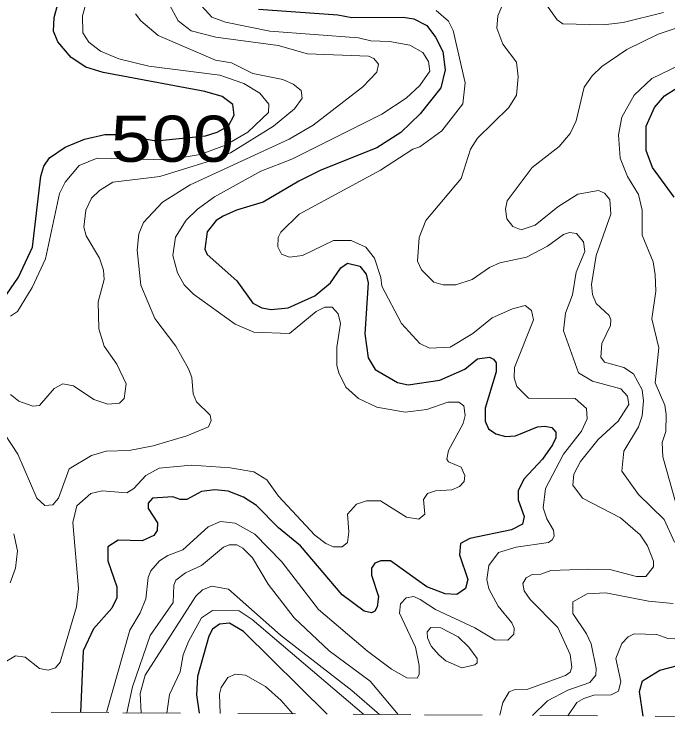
# Model space of a CAD drawing. Extents: x 577 to 602.9, y 7483.8 to 7511.6.
# Drawn here: x 599.345 to 600.48, y 7483.775 to 7485.008 of the extents above; entities that cross this region are included whole.
import ezdxf
from ezdxf.enums import TextEntityAlignment as Align

# ---------------------------------------------------------------- set-up
doc = ezdxf.new("R2010")
doc.units = 0
doc.header["$LTSCALE"] = 0.032
doc.linetypes.add('SHORT_DASHED', pattern=[2.7, 1.5, -1.2])
for name, color, linetype, lineweight in [('1', 7, 'Continuous', 25), ('2', 7, 'Continuous', 13), ('62', 7, 'SHORT_DASHED', 13)]:
    doc.layers.add(name, color=color, linetype=linetype, lineweight=lineweight)
doc.layers.add('61', color=7, linetype='Continuous')

msp = doc.modelspace()

# ---------------------------------------------------------------- linework, layer by layer
at = {"layer": '1'}
for points in [[(599.7065, 7484.8652), (599.6763, 7484.8739), (599.4998, 7484.9065), (599.4695, 7484.9161), (599.4441, 7484.9328), (599.421, 7484.9598), (599.4139, 7484.9781), (599.4147, 7485.002), (599.421, 7485.025), (599.4282, 7485.0369), (599.4847, 7485.0982), (599.5713, 7485.1666), (599.7455, 7485.3129), (599.7749, 7485.3439), (599.8075, 7485.3908), (599.821, 7485.4298), (599.8242, 7485.4886), (599.7987, 7485.5888), (599.7924, 7485.6484), (599.7924, 7485.6961), (599.8051, 7485.7542)], [(599.7693, 7485.0163), (599.9069, 7485.0067), (599.9315, 7485.002), (600.0206, 7485.0028), (600.0389, 7484.9996), (600.0612, 7484.9884), (600.0763, 7484.9678), (600.089, 7484.9431), (600.093, 7484.9113), (600.0858, 7484.8803), (600.05, 7484.835), (600.0166, 7484.8024), (599.9745, 7484.7761), (599.8775, 7484.7372), (599.8393, 7484.7181), (599.7773, 7484.6815), (599.7312, 7484.668), (599.7081, 7484.6576), (599.6962, 7484.6497), (599.6803, 7484.6306), (599.6763, 7484.6004), (599.6803, 7484.5909), (599.732, 7484.5455), (599.7598, 7484.5066), (599.7749, 7484.4986), (599.7916, 7484.4954), (599.821, 7484.4986), (599.8671, 7484.5193), (599.8942, 7484.5416), (599.9125, 7484.5678), (599.9236, 7484.5757), (599.9451, 7484.571), (599.9562, 7484.5567), (599.9594, 7484.5416), (599.9538, 7484.4533), (599.9594, 7484.4119), (599.9721, 7484.3913), (600.0103, 7484.369), (600.0293, 7484.365), (600.0842, 7484.373), (600.1272, 7484.3921), (600.1494, 7484.4103), (600.1701, 7484.4127), (600.1773, 7484.4096)], [(600.4905, 7484.6903), (600.4532, 7484.7419), (600.442, 7484.7714), (600.442, 7484.8135), (600.4564, 7484.8461), (600.4739, 7484.866), (600.4977, 7484.8811)], [(599.3328, 7484.5225), (599.3527, 7484.5519), (599.3773, 7484.6036), (599.3916, 7484.7268), (599.3972, 7484.7443), (599.4067, 7484.7586), (599.4338, 7484.7769), (599.4672, 7484.7912), (599.5029, 7484.7992), (599.5284, 7484.7992), (599.592, 7484.7883), (599.6776, 7484.7968), (599.6978, 7484.8032), (599.7176, 7484.8143), (599.7272, 7484.8326), (599.7248, 7484.8509), (599.7065, 7484.8652)], [(600.1773, 7484.4096), (600.182, 7484.4032), (600.182, 7484.3873), (600.1629, 7484.3245), (600.1629, 7484.3022), (600.1685, 7484.2887), (600.1812, 7484.2799), (600.1979, 7484.2752), (600.2154, 7484.2768), (600.2536, 7484.2919), (600.2663, 7484.2935), (600.2782, 7484.2911), (600.2854, 7484.2831), (600.2854, 7484.2728), (600.2798, 7484.2609), (600.2623, 7484.2362), (600.2297, 7484.2012), (600.2202, 7484.1813), (600.2202, 7484.1654), (600.2305, 7484.1368), (600.2273, 7484.1233), (600.2083, 7484.1137), (600.1359, 7484.0986), (600.12, 7484.0899), (600.1184, 7484.07), (600.1327, 7484.0271), (600.1287, 7484.012), (600.1136, 7484.0016), (600.093, 7484.0024), (600.0612, 7484.0144), (599.9983, 7484.0597), (599.9816, 7484.0597), (599.9713, 7484.0557), (599.9657, 7484.047), (599.9657, 7484.035), (599.9777, 7483.9977), (599.9753, 7483.9802), (599.9713, 7483.9722), (599.9657, 7483.9698), (599.953, 7483.9722), (599.9148, 7484.0008), (599.8425, 7484.0859), (599.8043, 7484.1169), (599.7661, 7484.1559), (599.7431, 7484.1702), (599.7168, 7484.1805), (599.6938, 7484.1829), (599.6707, 7484.1797), (599.6453, 7484.1662), (599.6333, 7484.1662), (599.6206, 7484.171), (599.5856, 7484.1686), (599.5777, 7484.1599), (599.5777, 7484.1503), (599.5944, 7484.1257), (599.5936, 7484.1122), (599.588, 7484.1034), (599.5674, 7484.0947), (599.526, 7484.0955), (599.5077, 7484.0843), (599.5077, 7484.0597), (599.5236, 7484.0144), (599.5236, 7483.9953), (599.5149, 7483.9778), (599.4831, 7483.942), (599.465, 7483.9037), (599.4604, 7483.7968)], [(599.8885, 7483.7939), (599.7431, 7483.9372), (599.7192, 7483.9515), (599.7017, 7483.9499), (599.6898, 7483.9412), (599.6834, 7483.9293), (599.6636, 7483.8593), (599.662, 7483.8275), (599.6665, 7483.7954)], [(600.4367, 7483.7904), (600.4304, 7483.833), (600.4358, 7483.8515), (600.4659, 7483.8704), (600.5104, 7483.8816)]]:
    msp.add_lwpolyline(points, dxfattribs=at)
at = {"layer": '2'}
for points in [[(599.6588, 7485.0354), (599.6882, 7485.0028), (599.7121, 7484.994), (599.7892, 7484.9781), (599.9427, 7484.967), (599.9641, 7484.9614), (599.9967, 7484.9606), (600.0317, 7484.9542), (600.0548, 7484.9415), (600.0643, 7484.9256), (600.0667, 7484.9089), (600.0492, 7484.8843), (600.0254, 7484.862), (599.9832, 7484.8342), (599.8274, 7484.7563), (599.7733, 7484.7356), (599.693, 7484.691), (599.6636, 7484.6696), (599.6437, 7484.6505), (599.6254, 7484.6211), (599.6206, 7484.5893), (599.6286, 7484.559), (599.6405, 7484.5384), (599.6564, 7484.5225), (599.7288, 7484.47), (599.7614, 7484.4565), (599.8234, 7484.4541), (599.8695, 7484.4923), (599.8846, 7484.4994), (599.8973, 7484.4994), (599.9077, 7484.4883), (599.9117, 7484.4716), (599.9053, 7484.4302), (599.9053, 7484.3984), (599.9085, 7484.3857), (599.9212, 7484.361), (599.9427, 7484.3412), (599.9745, 7484.3261), (600.0238, 7484.3173), (600.0612, 7484.3221), (600.0977, 7484.3348), (600.1168, 7484.3348), (600.1256, 7484.3284), (600.1279, 7484.3117), (600.1248, 7484.2982), (600.0993, 7484.2513), (600.0961, 7484.2362), (600.0993, 7484.2314), (600.1208, 7484.2219), (600.1272, 7484.2076), (600.1264, 7484.1972), (600.1184, 7484.1885), (600.1049, 7484.1829), (600.0763, 7484.1813), (600.0627, 7484.1766), (600.0556, 7484.1662), (600.058, 7484.1408), (600.0476, 7484.132), (600.0262, 7484.1352), (599.9808, 7484.1638), (599.957, 7484.1638), (599.9395, 7484.1583), (599.9236, 7484.1408), (599.926, 7484.1098), (599.9236, 7484.0915), (599.9148, 7484.0843), (599.8997, 7484.0843), (599.8862, 7484.0899), (599.8671, 7484.1042), (599.8043, 7484.1718), (599.7836, 7484.2004), (599.7614, 7484.2139), (599.72, 7484.2211), (599.6532, 7484.2259), (599.5968, 7484.2203), (599.5737, 7484.2076), (599.553, 7484.1853), (599.5411, 7484.1774)], [(600.2631, 7485.0322), (600.2878, 7484.998), (600.2973, 7484.9908), (600.3673, 7484.9892), (600.4023, 7484.9932), (600.4723, 7485.0107)], [(599.6143, 7485.025), (599.6302, 7484.9964), (599.6524, 7484.9789), (599.6954, 7484.9678), (599.8035, 7484.9535), (599.8544, 7484.9391), (599.9602, 7484.9352), (599.9697, 7484.9312), (599.9777, 7484.9209), (599.9745, 7484.9073), (599.9506, 7484.8819), (599.864, 7484.8151), (599.8226, 7484.7912), (599.6508, 7484.7117), (599.6031, 7484.6815), (599.5697, 7484.6465), (599.5618, 7484.6266), (599.5586, 7484.5988), (599.565, 7484.5376), (599.5896, 7484.4803), (599.6262, 7484.4318), (599.6477, 7484.3929), (599.654, 7484.3777), (599.6559, 7484.3493), (599.662, 7484.3356), (599.6858, 7484.3125), (599.6874, 7484.303), (599.6827, 7484.2919), (599.6453, 7484.2768), (599.5864, 7484.2593), (599.5451, 7484.2513), (599.5053, 7484.2497), (599.4799, 7484.2426), (599.4409, 7484.2195), (599.4226, 7484.1686), (599.4123, 7484.1567), (599.3988, 7484.1559), (599.3845, 7484.1686), (599.3519, 7484.245), (599.3169, 7484.2966)], [(599.7439, 7484.8875), (599.7025, 7484.9018), (599.5793, 7484.9177), (599.5268, 7484.9304), (599.495, 7484.9439), (599.4751, 7484.959), (599.4648, 7484.9757), (599.464, 7485.0051), (599.4711, 7485.0298)], [(600.1881, 7483.7919), (600.1932, 7483.814), (600.2043, 7483.8323), (600.213, 7483.8362), (600.2369, 7483.837), (600.3021, 7483.8609), (600.31, 7483.8664), (600.3132, 7483.8752), (600.31, 7483.8975), (600.2886, 7483.9444), (600.2409, 7483.9929), (600.2305, 7484.008), (600.2281, 7484.0207), (600.2337, 7484.0303), (600.244, 7484.0358), (600.2592, 7484.0366), (600.2766, 7484.043), (600.3426, 7484.0454), (600.3792, 7484.0446), (600.4253, 7484.0326), (600.4412, 7484.0326), (600.4548, 7484.0493), (600.4548, 7484.0589), (600.4444, 7484.0859), (600.4317, 7484.105), (600.3975, 7484.1344), (600.3315, 7484.1686), (600.3148, 7484.1909), (600.3164, 7484.21), (600.3283, 7484.2322), (600.3586, 7484.2704), (600.3935, 7484.3022), (600.4118, 7484.3308), (600.4094, 7484.3451), (600.3983, 7484.3579), (600.349, 7484.3714), (600.3244, 7484.3857), (600.2989, 7484.4589), (600.3021, 7484.4891), (600.314, 7484.5209), (600.3204, 7484.5606), (600.3355, 7484.5964), (600.3331, 7484.6131), (600.3212, 7484.6274), (600.3092, 7484.629), (600.2989, 7484.6258), (600.2711, 7484.6052), (600.2345, 7484.5861), (600.1884, 7484.5765), (600.1701, 7484.5686), (600.1399, 7484.5479), (600.112, 7484.5384), (600.0898, 7484.5384), (600.0739, 7484.5431), (600.0524, 7484.5646), (600.0453, 7484.5797), (600.0484, 7484.6203), (600.0596, 7484.6497), (600.1208, 7484.7229), (600.1375, 7484.7737), (600.1494, 7484.7928), (600.2035, 7484.8461), (600.217, 7484.8676), (600.2202, 7484.8994), (600.217, 7484.9248), (600.1932, 7484.9558), (600.1828, 7484.9837), (600.1844, 7485.0051), (600.1916, 7485.021)], [(599.5059, 7483.7965), (599.5459, 7483.9396), (599.5642, 7483.9698), (599.5737, 7483.9937), (599.5777, 7484.031), (599.5825, 7484.0422), (599.5976, 7484.0597), (599.6119, 7484.0692), (599.6381, 7484.0788), (599.6819, 7484.1185), (599.7033, 7484.1281), (599.7288, 7484.1249), (599.763, 7484.1058), (599.8099, 7484.0581), (599.8735, 7483.9754), (599.9586, 7483.903), (599.9999, 7483.872), (600.027, 7483.8569), (600.0445, 7483.8561), (600.0484, 7483.8625), (600.0484, 7483.8784), (600.0421, 7483.9102), (600.0142, 7483.969), (600.0158, 7483.9849), (600.0254, 7483.9953), (600.0389, 7483.9977), (600.05, 7483.9929), (600.0763, 7483.9754), (600.1446, 7483.9436), (600.1796, 7483.9229), (600.2019, 7483.9221), (600.2122, 7483.9324), (600.213, 7483.9428), (600.2091, 7483.9523), (600.1852, 7483.981), (600.1693, 7484.0112), (600.1653, 7484.0271), (600.1693, 7484.0517), (600.186, 7484.074), (600.2162, 7484.0835), (600.2727, 7484.0915), (600.279, 7484.0963), (600.2822, 7484.1026), (600.2814, 7484.113), (600.2695, 7484.1328), (600.2631, 7484.1519), (600.2671, 7484.1853), (600.2989, 7484.245), (600.3299, 7484.2847), (600.3395, 7484.3062), (600.3387, 7484.3237), (600.3188, 7484.3412), (600.2377, 7484.342), (600.2178, 7484.3618), (600.213, 7484.377), (600.2138, 7484.3952), (600.2464, 7484.4779), (600.2432, 7484.4938), (600.2321, 7484.5026), (600.2099, 7484.497), (600.1749, 7484.4811), (600.1415, 7484.4541), (600.1017, 7484.4302), (600.0659, 7484.4286), (600.0492, 7484.4366), (600.0174, 7484.4716), (599.9832, 7484.536), (599.9816, 7484.5511), (599.9705, 7484.5845), (599.9554, 7484.6036), (599.93, 7484.6155), (599.8997, 7484.6155), (599.8457, 7484.5893), (599.8234, 7484.5861), (599.8091, 7484.5916), (599.8027, 7484.6044), (599.8035, 7484.6203), (599.8083, 7484.6298), (599.8401, 7484.6608), (599.9808, 7484.7372), (600.0373, 7484.7737), (600.0492, 7484.7777), (600.0874, 7484.8056), (600.124, 7484.8525), (600.1279, 7484.889), (600.1073, 7484.9797), (600.0993, 7484.9956), (600.0779, 7485.0139)], [(599.8115, 7484.8946), (599.7598, 7484.9049), (599.7224, 7484.9232), (599.6946, 7484.928), (599.5952, 7484.9709), (599.565, 7484.9964), (599.5562, 7485.0083)], [(600.4913, 7484.0923), (600.4731, 7484.1312), (600.4285, 7484.175), (600.3999, 7484.2155), (600.4031, 7484.2497), (600.4285, 7484.2919), (600.4349, 7484.311), (600.4373, 7484.3372), (600.4349, 7484.3563), (600.4198, 7484.3841), (600.4031, 7484.3952), (600.3697, 7484.404), (600.3633, 7484.4127), (600.3649, 7484.4366), (600.38, 7484.4676), (600.3808, 7484.4779), (600.3776, 7484.4851), (600.3554, 7484.5058), (600.349, 7484.5217), (600.3474, 7484.5392), (600.3554, 7484.5893), (600.3808, 7484.6608), (600.3792, 7484.6863), (600.3697, 7484.6974), (600.3593, 7484.7022), (600.3236, 7484.6958), (600.2886, 7484.6736), (600.2496, 7484.6417), (600.225, 7484.6338), (600.2106, 7484.6394), (600.2003, 7484.6529), (600.1979, 7484.6696), (600.2011, 7484.6839), (600.244, 7484.7419), (600.291, 7484.7785), (600.31, 7484.8008), (600.3204, 7484.823), (600.3347, 7484.8811), (600.3482, 7484.901), (600.3649, 7484.9169), (600.4086, 7484.9463), (600.4627, 7484.9733), (600.508, 7484.9884)], [(600.4929, 7484.1623), (600.4707, 7484.2402), (600.4699, 7484.2648), (600.4762, 7484.2839), (600.477, 7484.3133), (600.4746, 7484.33), (600.4579, 7484.3682), (600.4643, 7484.4294), (600.4516, 7484.4795), (600.4587, 7484.5272), (600.4579, 7484.5559), (600.454, 7484.5781), (600.4349, 7484.6243), (600.4349, 7484.668), (600.4285, 7484.695), (600.4094, 7484.726), (600.3967, 7484.7578), (600.3943, 7484.7984), (600.3999, 7484.8294), (600.4214, 7484.8676), (600.4516, 7484.8962), (600.5001, 7484.9193)], [(599.3391, 7484.3483), (599.3534, 7484.3364), (599.3781, 7484.3277), (599.3892, 7484.3292), (599.4147, 7484.3587), (599.4298, 7484.3666), (599.4481, 7484.3634), (599.4839, 7484.3396), (599.5077, 7484.3316), (599.5284, 7484.3332), (599.5363, 7484.3412), (599.5395, 7484.3666), (599.5236, 7484.4008), (599.5014, 7484.4318), (599.4926, 7484.462), (599.491, 7484.509), (599.5014, 7484.5479), (599.5006, 7484.5638), (599.4934, 7484.5845), (599.4703, 7484.6235), (599.4664, 7484.6386), (599.4695, 7484.668), (599.4799, 7484.6887), (599.4934, 7484.7022), (599.5165, 7484.7165), (599.5984, 7484.726), (599.6803, 7484.7515), (599.7208, 7484.7674), (599.7956, 7484.8135), (599.8321, 7484.8437), (599.8449, 7484.862), (599.8433, 7484.8755), (599.8298, 7484.8867), (599.8115, 7484.8946)], [(599.3391, 7484.4843), (599.3511, 7484.4923), (599.3765, 7484.5336), (599.3996, 7484.5837), (599.4242, 7484.6966), (599.4338, 7484.7165), (599.4585, 7484.7452), (599.4895, 7484.7581), (599.6121, 7484.7551), (599.6681, 7484.7642), (599.7121, 7484.7809), (599.751, 7484.8032), (599.7868, 7484.8374), (599.7876, 7484.8517), (599.7717, 7484.8708), (599.7439, 7484.8875)], [(599.5411, 7484.1774), (599.4982, 7484.1813), (599.4783, 7484.1766), (599.4544, 7484.1551), (599.4473, 7484.1265), (599.4568, 7484.012), (599.4536, 7483.9802), (599.425, 7483.8839), (599.4171, 7483.8744), (599.4043, 7483.8704), (599.3892, 7483.8728), (599.3646, 7483.8927), (599.3479, 7483.8951), (599.289, 7483.8601)], [(599.3383, 7484.0215), (599.3479, 7484.047), (599.3511, 7484.0772), (599.3447, 7484.1066)], [(599.5409, 7483.7963), (599.5506, 7483.8414), (599.5817, 7483.9301), (599.6214, 7483.9873), (599.6222, 7484.0175), (599.6262, 7484.0263), (599.6429, 7484.039), (599.6707, 7484.0517), (599.7089, 7484.0835), (599.7184, 7484.0875), (599.732, 7484.0875), (599.7423, 7484.0819), (599.759, 7484.0652), (599.786, 7484.0191), (599.8313, 7483.9611), (599.8918, 7483.9038), (599.9633, 7483.8513), (600.0118, 7483.7931)], [(599.9795, 7483.7933), (599.9315, 7483.835), (599.8074, 7483.9309), (599.7176, 7484.0104), (599.6882, 7484.0159), (599.6723, 7484.0096), (599.6604, 7483.9984), (599.5729, 7483.8612), (599.5641, 7483.8296), (599.5657, 7483.7961)], [(600.2446, 7483.7916), (600.2711, 7483.8171), (600.3061, 7483.8354), (600.3442, 7483.849), (600.3546, 7483.8617), (600.3554, 7483.8728), (600.3466, 7483.9157), (600.3387, 7483.9332), (600.3148, 7483.9682), (600.3148, 7483.9889), (600.3395, 7484.0024), (600.3721, 7484.004), (600.446, 7483.9897), (600.489, 7483.9857)], [(599.6104, 7483.7958), (599.615, 7483.8279), (599.6333, 7483.8672), (599.6389, 7483.8967), (599.6477, 7483.9197), (599.6707, 7483.9611), (599.6898, 7483.9738), (599.7359, 7483.973), (599.7586, 7483.9581), (599.9521, 7483.7935)], [(600.3064, 7483.7912), (600.322, 7483.814), (600.3339, 7483.8211), (600.3514, 7483.8267), (600.3816, 7483.8275), (600.3943, 7483.8338), (600.3983, 7483.8505), (600.3896, 7483.8903), (600.3999, 7483.9165), (600.411, 7483.9277), (600.4214, 7483.9332), (600.4603, 7483.9317), (600.4794, 7483.9253), (600.5041, 7483.9237)], [(599.7031, 7483.7952), (599.7017, 7483.8283), (599.7049, 7483.8402), (599.716, 7483.8577), (599.7296, 7483.8633), (599.7471, 7483.8617), (599.7815, 7483.8417), (599.8085, 7483.8177), (599.8291, 7483.7943)]]:
    msp.add_lwpolyline(points, dxfattribs=at)
msp.add_lwpolyline([(600.0826, 7483.8959), (600.0946, 7483.8863), (600.1224, 7483.8744), (600.1446, 7483.8792), (600.1486, 7483.8831), (600.1486, 7483.8903), (600.1343, 7483.9102), (600.116, 7483.9277), (600.0858, 7483.9436), (600.0683, 7483.9444), (600.0619, 7483.9364), (600.0627, 7483.9261), (600.0691, 7483.9118)], close=True, dxfattribs=at)
at = {"layer": '62'}
msp.add_lwpolyline([(593.7709, 7483.8329), (594.2948, 7483.8296), (594.8187, 7483.8264), (595.3426, 7483.8231), (595.8665, 7483.8198), (596.3904, 7483.8165), (596.9143, 7483.8132), (597.4382, 7483.8098), (597.9621, 7483.8065), (598.486, 7483.8031), (599.0099, 7483.7997), (599.5338, 7483.7963), (600.0577, 7483.7928), (600.5816, 7483.7894), (601.1055, 7483.7859), (601.6294, 7483.7824), (602.1533, 7483.7789), (602.6772, 7483.7754)], dxfattribs=at)

# ---------------------------------------------------------------- texts
at = {"layer": '61', "width": 1.2}
msp.add_text('500', height=0.08, dxfattribs=at).set_placement((599.6199, 7484.7518), align=Align.CENTER)

doc.saveas('drawing.dxf')
